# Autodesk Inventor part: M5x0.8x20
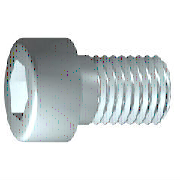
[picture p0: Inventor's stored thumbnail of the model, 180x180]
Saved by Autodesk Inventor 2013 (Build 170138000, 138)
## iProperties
IsCustomPart: 0
Created: 2015-11
Part Number: M5x0.8x20
Material: 스테인리스강
Description: 6각머리 태핑 나사
Document SubType Name: Modeling
Standard: KS B 1003
Designer: mdu
Standards Organization: KS
Language: ko-KR
Size Designation: M 5 x 20
Categories: <MemberInstance><Categories><Category DisplayName="조임쇠" InternalName="e4da775c-781d-43d5-af7c-5136215cf5a6" Mnemonic="FSTN"><Category DisplayName="볼트" InternalN
Density: 1 g/cm^3
Author: mdu
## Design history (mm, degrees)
sketch "스케치1"
  geometry: L1 (-1.167, 0)-(20, 0); L2 (20, 0)-(20, 2.5); L3 (20, 2.5)-(2, 2.5); L4 (2, 2.5)-(1.509, 2.5); L5 (1.509, 2.5)-(0, 2.5); L6 (0, 2.5)-(0, 4.25); L7 (0, 4.25)-(-5, 4.25); L8 (-5, 4.25)-(-5, 2.309); L9 (-5, 2.309)-(-2.5, 2.309); L10 (-2.5, 2.309)-(-1.167, 0); L11 (-10, 0)-(25, 0) reference; L12 (0, -0.85)-(0, 5.1) reference; L13 (2, 2.5)-(0, 2.5)
  constraints: 22 end point, 6 parallel, 2 collinear, 2 perpendicular, 1 horizontal, 1 point on line
  dimensions: "d1" = 18 distance from line of L3.end L2 (= GEL); "d2" = 0.49086 distance of L4.end L3.end (computed from GAL); "d3" = 5 distance between parallel lines of L8 L6 (= KOH); "d4" = 2.5 distance of L8.end L9.end (= INTI); "d5" = 60 deg angle of L10 L1; "d6" = 5 diameter of L3 L1 (= GD); "d7" = 5 diameter of L5 L1 (= BDM); "d8" = 4.6188 diameter of L9 L1 (= 1.1547 x SW); "d9" = 8.5 diameter of L7 L1 (= KOD); "d26" = 20 distance between parallel lines of L12 L2 (= NLG)
revolve "본체" sketch "스케치1" stored, may be unused: angle "d10" = 90 deg
sketch "스케치2"
  geometry: L1 (0, -5.95)-(0, 5.95) reference; L2 (-5.95, 0)-(5.95, 0) reference; L3 (2.309, 0)-(1.155, -2); L4 (1.155, -2)-(-1.155, -2); L5 (-1.155, -2)-(-2.309, 0); L6 (-2.309, 0)-(-1.155, 2); L7 (-1.155, 2)-(1.155, 2); L8 (1.155, 2)-(2.309, 0); 2 further points
  constraints: 12 end point, 1 coincident, 1 horizontal alignment, 1 point on line, 12 other
extrude "슬롯" join sketch "스케치2" stored distance "d11" = 10; taper "d12" = 0 deg
workplane "Work Plane1"
fillet "Fillet2" dims "d30" = 0.1 (= R)
body "Solid1"
fillet "모깎기1" dims "d17" = 0.5 (= RR)
feature "스레드" dims "d13" = 18 (= GEL), "d14" = 0
chamfer "모따기1" distance "d15" = 0.49076 (= -0.5 x SPD + 0.5 x GD); stored, may be unused: second distance "d16" = 0.49076 (= GUL), angle "d27" = 45 deg
other parameters: "GD" = 5 (= NND) [user parameter; used in 2 equation terms], "NLG" = 20 [user parameter; used in 1 equation term], "GEL" = 18 [user parameter; used in 2 equation terms], "KOD" = 8.5 [user parameter; used in 1 equation term], "KOH" = 5 [user parameter; used in 1 equation term], "INTI" = 2.5 [user parameter; used in 1 equation term], "GAL" = 0.49076 (= 0.61345 x PTC) [user parameter; used in 1 equation term], "GUL" = 0.49076 (= 0.61345 x PTC) [user parameter; used in 1 equation term], "BDM" = 5 (= NND) [user parameter; used in 1 equation term], "SW" = 4 [user parameter; used in 2 equation terms], "RR" = 0.5 [user parameter; used in 1 equation term], "SPD" = 4.01848 (= NND - 1.2269 x PTC) [user parameter; used in 1 equation term], "d19" = 0, "d28" = 0, "d29" = 0, "R" = 0.1 [user parameter; used in 1 equation term], "PHH" = 0.2 [user parameter], "GD1" = 4.01848 (= THREADDIA - 1.2269 x PTC) [user parameter], "THREADDIA" = 5 [user parameter; used in 1 equation term], "FAWI" = 45 deg [user parameter], "TPU" = 12.5 (computed from PTC) [user parameter], "PTC" = 0.8 [user parameter; used in 5 equation terms], "NND" = 5 [user parameter; used in 3 equation terms], "TOA" = 30 deg [user parameter], "E0" = 4.62 (= 1.155 x SW) [user parameter]
